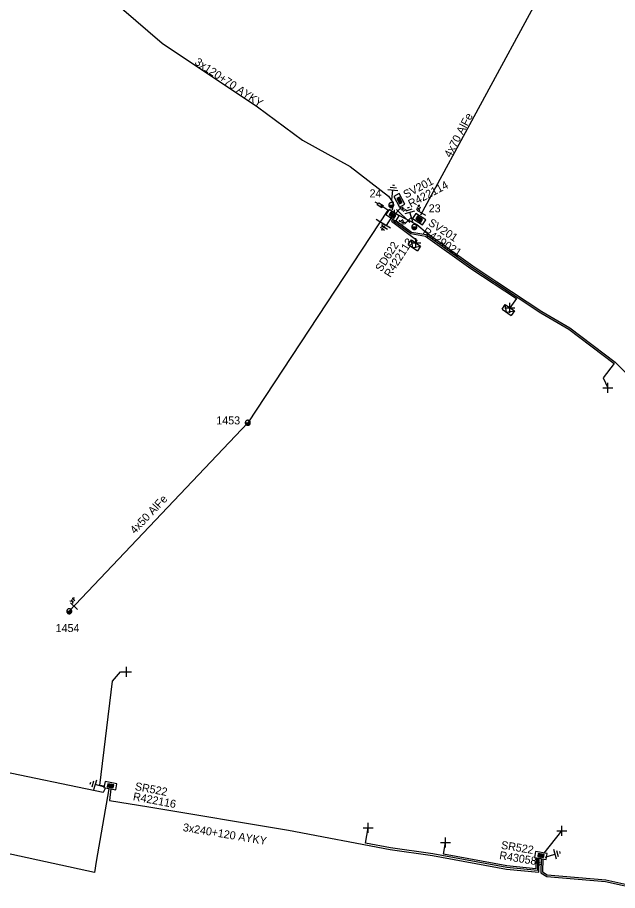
# Model space of a CAD drawing. Extents: x -540466 to -537383, y -1184038 to -1179972.
# Drawn here: x -537932 to -537857, y -1180517.1 to -1180408 of the extents above; entities that cross this region are included whole.
import ezdxf

# ---------------------------------------------------------------- set-up
doc = ezdxf.new("R2010")
doc.units = 0
for name, color, linetype in [('Vrstva 1', 7, 'Continuous'), ('Vrstva 13', 7, 'Continuous'), ('Vrstva 14', 7, 'Continuous'), ('Vrstva 15', 7, 'Continuous'), ('Vrstva 16', 7, 'Continuous'), ('Vrstva 18', 7, 'Continuous'), ('Vrstva 2', 7, 'Continuous'), ('Vrstva 28', 7, 'Continuous'), ('Vrstva 29', 7, 'Continuous'), ('Vrstva 30', 7, 'Continuous'), ('Vrstva 31', 7, 'Continuous'), ('Vrstva 34', 7, 'Continuous'), ('Vrstva 5', 7, 'Continuous'), ('Vrstva 52', 7, 'Continuous'), ('Vrstva 59', 7, 'Continuous'), ('Vrstva 6', 7, 'Continuous'), ('Vrstva 8', 7, 'Continuous'), ('Vrstva 9', 7, 'Continuous')]:
    doc.layers.add(name, color=color, linetype=linetype)

# ---------------------------------------------------------------- blocks, each defined once
blk = doc.blocks.new('NN440')
at = {"layer": 'Vrstva 2'}
for points in [[(0.63, 0), (0.63, 0.06), (0.62, 0.13), (0.6, 0.19), (0.58, 0.25), (0.55, 0.31), (0.51, 0.37), (0.47, 0.42), (0.42, 0.46), (0.37, 0.51), (0.32, 0.54), (0.26, 0.57), (0.2, 0.59), (0.13, 0.61), (0.07, 0.62), (0, 0.63), (-0.06, 0.62), (-0.13, 0.61), (-0.19, 0.59), (-0.26, 0.57), (-0.31, 0.54), (-0.37, 0.51), (-0.42, 0.46), (-0.47, 0.42), (-0.51, 0.37), (-0.54, 0.31), (-0.57, 0.25), (-0.6, 0.19), (-0.62, 0.13), (-0.63, 0.06), (-0.63, 0), (-0.63, -0.07), (-0.62, -0.14), (-0.6, -0.2), (-0.57, -0.26), (-0.54, -0.32), (-0.51, -0.37), (-0.47, -0.43), (-0.42, -0.47), (-0.37, -0.51), (-0.31, -0.55), (-0.26, -0.58), (-0.19, -0.6), (-0.13, -0.62), (-0.06, -0.63), (0, -0.63), (0.07, -0.63), (0.13, -0.62), (0.2, -0.6), (0.26, -0.58), (0.32, -0.55), (0.37, -0.51), (0.42, -0.47), (0.47, -0.43), (0.51, -0.37), (0.55, -0.32), (0.58, -0.26), (0.6, -0.2), (0.62, -0.14), (0.63, -0.07), (0.63, 0)], [(-0.63, 0), (0.63, 0)], [(-0.6, -0.18), (0.57, -0.18)], [(-0.51, -0.32), (0.5, -0.32)], [(-0.37, -0.47), (0.35, -0.47)]]:
    blk.add_lwpolyline(points, dxfattribs=at)
blk = doc.blocks.new('NN840')
at = {"layer": 'Vrstva 15'}
for points in [[(0, 0.62), (0, -0.63)], [(-0.75, -0.71), (-0.75, -0.66)], [(-0.73, -0.76), (-0.75, -0.71)], [(-0.66, -0.8), (-0.73, -0.76)], [(-0.63, -0.8), (-0.66, -0.8)], [(-0.56, -0.76), (-0.63, -0.8)], [(-0.54, -0.71), (-0.56, -0.76)], [(-0.54, -0.38), (-0.54, -0.71)], [(-0.33, -0.38), (-0.33, -0.8)], [(-0.33, -0.64), (-0.13, -0.38)], [(-0.26, -0.56), (-0.09, -0.8)]]:
    blk.add_lwpolyline(points, dxfattribs=at)
blk = doc.blocks.new('NN800')
at = {"layer": 'Vrstva 1'}
for points in [[(-0.44, 0.44), (0.44, -0.44)], [(-0.44, -0.44), (0.44, 0.44)]]:
    blk.add_lwpolyline(points, dxfattribs=at)
blk = doc.blocks.new('NN820')
at = {"layer": 'Vrstva 13'}
for points in [[(0, 0), (0, -1.05)], [(-0.16, -0.81), (0.16, -0.81)], [(-0.16, -1.47), (-0.16, -0.81)], [(0, -1.05), (-0.06, -0.93)], [(0, -1.05), (0.06, -0.93)], [(0.16, -0.81), (0.16, -1.47)], [(0.16, -1.47), (-0.16, -1.47)], [(0, -1.47), (0, -1.87)]]:
    blk.add_lwpolyline(points, dxfattribs=at)
blk = doc.blocks.new('NN620')
at = {"layer": 'Vrstva 8'}
for points in [[(0.75, 0), (-0.75, 0)], [(-0.75, 0), (-0.75, -0.75)], [(0.75, -0.75), (0.75, 0)], [(-0.75, -0.75), (0.75, -0.75)], [(0.37, -0.18), (-0.38, -0.18)], [(-0.38, -0.18), (-0.38, -0.56)], [(-0.38, -0.56), (0.37, -0.56)], [(0.32, -0.23), (-0.33, -0.23)], [(-0.33, -0.23), (-0.33, -0.51)], [(-0.33, -0.51), (0.32, -0.51)], [(0.27, -0.27), (-0.28, -0.27)], [(-0.28, -0.27), (-0.28, -0.46)], [(-0.28, -0.46), (0.27, -0.46)], [(0.23, -0.32), (-0.23, -0.32)], [(-0.23, -0.32), (-0.23, -0.42)], [(-0.23, -0.42), (0.23, -0.42)], [(-0.19, -0.37), (0.19, -0.37)], [(0.23, -0.42), (0.23, -0.32)], [(0.27, -0.46), (0.27, -0.27)], [(0.32, -0.51), (0.32, -0.23)], [(0.37, -0.56), (0.37, -0.18)]]:
    blk.add_lwpolyline(points, dxfattribs=at)
blk = doc.blocks.new('NN630')
at = {"layer": 'Vrstva 9'}
for points in [[(0, -0.7), (-0.7, 0)], [(-0.7, -0.7), (-0.7, 0), (0.7, 0), (0.7, -0.7)], [(-0.7, -0.7), (0.7, -0.7)], [(0, -0.7), (0.7, 0)]]:
    blk.add_lwpolyline(points, dxfattribs=at)
blk = doc.blocks.new('NN810')
at = {"layer": 'Vrstva 14'}
for points in [[(0, -0.64), (0, -1.89)], [(0.63, -1.89), (-0.62, -1.89)], [(0.39, -2.2), (-0.4, -2.2)], [(0, -2.52), (-0.12, -2.52)], [(0.14, -2.52), (0, -2.52)]]:
    blk.add_lwpolyline(points, dxfattribs=at)

msp = doc.modelspace()

# ---------------------------------------------------------------- linework, layer by layer
at = {"layer": 'Vrstva 1'}
for points in [[(-537861.91, -1180399.13), (-537866.7, -1180405.21), (-537881.64, -1180432.73)], [(-537885.71, -1180432.12), (-537903.21, -1180458.68), (-537925.53, -1180482.23)], [(-537882.98, -1180433.63), (-537884.64, -1180432.01)]]:
    msp.add_lwpolyline(points, dxfattribs=at)
at = {"layer": 'Vrstva 5'}
for points in [[(-537939.35, -1180386.68), (-537938.97, -1180386.33), (-537938.02, -1180387.3), (-537938.78, -1180388.38), (-537939.38, -1180388.81), (-537939.32, -1180391.24), (-537938.91, -1180391.9), (-537937.61, -1180391.8), (-537936.36, -1180391.28), (-537934.32, -1180392.76), (-537926.57, -1180399.08), (-537923.78, -1180401.49), (-537919.01, -1180406.85), (-537913.93, -1180411.26), (-537902, -1180419.18), (-537896.36, -1180423.37), (-537890.41, -1180426.66), (-537885.63, -1180430.34), (-537885.04, -1180431.2), (-537885.17, -1180432.07)], [(-537884.86, -1180432.45), (-537884.89, -1180432.07)], [(-537884.59, -1180432.61), (-537882.08, -1180433.9), (-537880.81, -1180434.99), (-537875.1, -1180439.06), (-537872.09, -1180441.05), (-537866.46, -1180444.78), (-537862.96, -1180446.83), (-537857.29, -1180451.1), (-537852.89, -1180455.49), (-537847.58, -1180461.71), (-537842.1, -1180467.52), (-537838.1, -1180472.04), (-537833.53, -1180476.8), (-537829.32, -1180481.34), (-537827.56, -1180486.21), (-537827.49, -1180486.95), (-537827.36, -1180486.93)], [(-537920.56, -1180504.4), (-537922.18, -1180513.5), (-537922.39, -1180514.88), (-537947.28, -1180509.47), (-537968.09, -1180505.09), (-537988.44, -1180499.35), (-537996.47, -1180497.39), (-538029.52, -1180488.84), (-538052, -1180479.18), (-538051.68, -1180477.71), (-538049.11, -1180472.13), (-538048.48, -1180471.68), (-538047.8, -1180470.31)], [(-537866.54, -1180513.18), (-537866.58, -1180514.91), (-537865.85, -1180515.36), (-537858.5, -1180516.01), (-537853.98, -1180517), (-537849.45, -1180517.13), (-537844.07, -1180516.16), (-537839.96, -1180515.78), (-537835.96, -1180515.9), (-537825.48, -1180515.88), (-537824.36, -1180515.37), (-537824.1, -1180514.31), (-537824.95, -1180510.27), (-537825.63, -1180503.87), (-537825.56, -1180502.07), (-537826.01, -1180499.69), (-537826.76, -1180494.17), (-537827.06, -1180489.39), (-537827.53, -1180487.76), (-537827.27, -1180487.69)], [(-537920.33, -1180504.44), (-537920.51, -1180505.86), (-537915.6, -1180506.68), (-537898.11, -1180509.6), (-537885.4, -1180512.01), (-537880.11, -1180512.74), (-537870.88, -1180514.46), (-537866.83, -1180514.85), (-537866.78, -1180513.14)]]:
    msp.add_lwpolyline(points, dxfattribs=at)
at = {"layer": 'Vrstva 52'}
for points in [[(-537885.07, -1180433.21), (-537885.27, -1180433.5), (-537882.92, -1180435.23), (-537882.09, -1180435.86), (-537882.19, -1180436.21)], [(-537884.91, -1180433.32), (-537885, -1180433.45), (-537882.84, -1180435.04), (-537881.01, -1180435.34), (-537875.33, -1180439.39), (-537869.64, -1180443.15), (-537870.46, -1180444.3)], [(-537884.68, -1180433.43), (-537882.76, -1180434.85), (-537880.93, -1180435.15), (-537875.21, -1180439.23), (-537866.57, -1180444.95), (-537863.07, -1180447), (-537857.42, -1180451.25), (-537858.79, -1180453.08), (-537858.23, -1180454.32)], [(-537921.15, -1180504.07), (-537921.72, -1180503.99), (-537920.13, -1180490.98), (-537919.12, -1180489.8), (-537918.38, -1180489.8)], [(-537920.99, -1180504.29), (-537921.28, -1180504.86), (-537934.95, -1180502.04), (-537935.03, -1180501.72)], [(-537866.99, -1180513.07), (-537867.02, -1180514.63), (-537870.85, -1180514.26), (-537880.08, -1180512.54), (-537885.37, -1180511.81), (-537888.49, -1180511.21), (-537888.16, -1180509.29)], [(-537867.19, -1180513.03), (-537867.21, -1180514.41), (-537870.82, -1180514.06), (-537878.75, -1180512.59), (-537878.5, -1180511.13)], [(-537866.33, -1180513.18), (-537866.37, -1180514.8), (-537865.79, -1180515.17), (-537858.47, -1180515.81), (-537853.96, -1180516.8), (-537849.46, -1180516.93), (-537844.1, -1180515.96), (-537839.97, -1180515.58), (-537840.24, -1180512.61), (-537839.95, -1180512.41)]]:
    msp.add_lwpolyline(points, dxfattribs=at)
at = {"layer": 'Vrstva 59'}
msp.add_lwpolyline([(-537866.18, -1180512.47), (-537863.95, -1180509.68)], dxfattribs=at)

# ---------------------------------------------------------------- block references
at = {"layer": 'Vrstva 13', "xscale": 0.5, "yscale": 0.5}
for p in [(-537885.28, -1180431.47), (-537882.4, -1180434.21), (-537903.21, -1180458.68), (-537925.53, -1180482.23)]:
    msp.add_blockref('NN440', p, dxfattribs=at)
at = {"layer": 'Vrstva 15'}
for p, rotation in [((-537885.28, -1180431.47), 173.72611106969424), ((-537884.92, -1180432.43), -31.51448884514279), ((-537882.41, -1180434.18), -163.60600554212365), ((-537920.45, -1180504.4), -105.75675561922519), ((-537866.64, -1180513.13), 106.88051946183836)]:
    msp.add_blockref('NN810', p, dxfattribs=dict(at, rotation=rotation))
at = {"layer": 'Vrstva 16', "rotation": -123.35733882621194}
msp.add_blockref('NN820', (-537885.71, -1180432.12), dxfattribs=at)
at = {"layer": 'Vrstva 18'}
for p, rotation in [((-537881.5, -1180432.47), -118.50124328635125), ((-537884.45, -1180432.19), 135.71725324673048), ((-537883.2, -1180433.41), -44.28274670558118), ((-537886.67, -1180433.57), 56.642660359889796), ((-537924.93, -1180481.6), -133.47525278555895)]:
    msp.add_blockref('NN840', p, dxfattribs=dict(at, rotation=rotation))
at = {"layer": 'Vrstva 28'}
for p, rotation in [((-537884.59, -1180431.06), 117.97499995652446), ((-537884.92, -1180432.43), -32.6446361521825), ((-537882, -1180433.55), 147.00800007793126), ((-537920.45, -1180504.4), 169.322161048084), ((-537866.64, -1180513.13), 170.6486499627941)]:
    msp.add_blockref('NN620', p, dxfattribs=dict(at, rotation=rotation))
at = {"layer": 'Vrstva 31'}
for p, rotation in [((-537882.19, -1180436.21), -34.28804455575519), ((-537870.46, -1180444.3), -35.16547768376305)]:
    msp.add_blockref('NN630', p, dxfattribs=dict(at, rotation=rotation))
at = {"layer": 'Vrstva 34'}
for p, rotation in [((-537882.19, -1180436.21), 45), ((-537870.46, -1180444.3), 45), ((-537858.23, -1180454.32), 45), ((-537918.38, -1180489.8), 45), ((-537888.16, -1180509.29), 45), ((-537863.95, -1180509.68), 44.99999995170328), ((-537878.5, -1180511.13), 45)]:
    msp.add_blockref('NN800', p, dxfattribs=dict(at, rotation=rotation))

# ---------------------------------------------------------------- texts
at = {"layer": 'Vrstva 14'}
for s, p in [('24', (-537887.99, -1180430.51)), ('23', (-537880.6, -1180432.38)), ('1453', (-537907.15, -1180458.88)), ('1454', (-537927.23, -1180484.83))]:
    msp.add_text(s, height=1, dxfattribs=at).set_placement(p)
at = {"layer": 'Vrstva 2'}
for s, rotation, p in [('4x70 AlFe', 62.107, (-537877.86, -1180425.62)), ('4x50 AlFe', 46.525, (-537917.32, -1180472.64))]:
    msp.add_text(s, height=1, rotation=rotation, dxfattribs=at).set_placement(p)
at = {"layer": 'Vrstva 29'}
for s, rotation, p in [('R422114', 27.975, (-537882.84, -1180431.82)), ('R429021', 327.008, (-537881.45, -1180435.01)), ('R422113', 57.355, (-537885.41, -1180440.59)), ('R422116', 349.322, (-537917.62, -1180505.83)), ('R430589', 350.649, (-537871.83, -1180513.19))]:
    msp.add_text(s, height=1, rotation=rotation, dxfattribs=at).set_placement(p)
at = {"layer": 'Vrstva 30'}
for s, rotation, p in [('SV201', 27.975, (-537883.45, -1180430.67)), ('SV201', 327.008, (-537880.75, -1180433.92)), ('SD622', 57.355, (-537886.51, -1180439.89)), ('SR522', 349.322, (-537917.38, -1180504.56)), ('SR522', 350.649, (-537871.61, -1180511.9))]:
    msp.add_text(s, height=1, rotation=rotation, dxfattribs=at).set_placement(p)
at = {"layer": 'Vrstva 6'}
for s, rotation, p in [('3x120+70 AYKY', 326.421, (-537909.94, -1180413.82)), ('3x240+120 AYKY', 350.522, (-537911.38, -1180509.69))]:
    msp.add_text(s, height=1, rotation=rotation, dxfattribs=at).set_placement(p)

doc.saveas('drawing.dxf')
